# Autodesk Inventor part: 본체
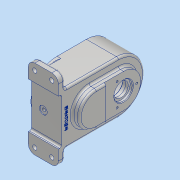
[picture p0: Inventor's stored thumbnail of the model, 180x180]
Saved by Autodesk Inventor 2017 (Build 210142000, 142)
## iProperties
Part Number: 본체
Material: 알루미늄 6061
Document SubType Name: Modeling
Designer: MRC
Density: 2.7 g/cm^3
Appearance: 알루미늄 - 평지
Mass: 756.755 g
Surface Area: 581.834 cm^2
Volume: 280.28 cm^3
Author: MRC
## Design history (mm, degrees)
sketch "스케치1"
  geometry: L1 (0, 40)-(-82, 40); L2 (-82, 40)-(-82, 61); L3 (-82, 61)-(-92, 61); L4 (-92, 61)-(-92, 35); L5 (-92, 35)-(-87, 35); L6 (-87, 35)-(-87, -35); L7 (-87, -35)-(-92, -35); L8 (-92, -35)-(-92, -61); L9 (-92, -61)-(-82, -61); L10 (-82, -61)-(-82, -40); L11 (-82, -40)-(0, -40); A1 r 40 centre (0, 0) between (0, -40) and (0, 40); 1 further point
  constraints: 22 end point, 6 perpendicular, 3 point on line, 2 horizontal, 2 point on circle, 2 tangent, 1 centre point, 1 coincident, 1 parallel, 1 vertical
  dimensions: "d0" = 80 diameter of A1; "d1" = 92 distance from line of L8 point (0, 0); "d2" = 10 distance of L8.end L9.end; "d3" = 70 distance between parallel lines of L7 L5; "d4" = 35 distance from line of L7 point (0, 0); "d5" = 5 distance between parallel lines of L8 L6; "d6" = 122 distance between parallel lines of L3 L9; "d7" = 61 distance from line of point (0, 0) L9
extrude "돌출1" new body sketch "스케치1" distance "d8" = 46; taper "d9" = 0 deg
sketch "스케치2"
  geometry: L1 (-40, 0)-(-40, -82) reference; L2 (40, -82)-(40, 0) reference; L3 (-40, -82)-(-40, 0) reference; L4 (-40, 0)-(-40, -45); L5 (40, 0)-(40, -45); A1 r 40 centre (0, 0) between (40, 0) and (-40, 0) reference; A2 r 40 centre (0, -45) between (-40, -45) and (40, -45); A3 r 40 centre (0, 0) between (40, 0) and (-40, 0); A4 r 40 centre (0, 0) between (40, 0) and (-40, 0) reference
  constraints: 6 end point, 4 point on circle, 2 centre point, 2 point on line, 2 tangent, 1 coincident, 1 concentric, 1 vertical
  dimensions: "d10" = 45 distance of A2.centre A1.centre
extrude "돌출2" join sketch "스케치2" distance "d11" = 3; taper "d12" = 0 deg
sketch "스케치3"
  geometry: L1 (0, 0)-(0, -45); L2 (-26, 0)-(-26, -45); L3 (26, -45)-(26, 0); A1 r 40 centre (0, 0) between (40, 0) and (-40, 0) reference; A2 r 26 centre (0, 0) between (26, 0) and (-26, 0); A3 r 26 centre (0, -45) between (-26, -45) and (26, -45); 1 further point
  constraints: 8 end point, 4 point on circle, 4 tangent, 2 centre point, 1 midpoint, 1 parallel, 1 vertical
  dimensions: "d13" = 52 diameter of A3; "d14" = 45 distance of L1.end L1.start
extrude "돌출3" join sketch "스케치3" distance "d15" = 11; taper "d16" = 0 deg
sketch "스케치4"
  geometry: L1 (-26, 0)-(-26, -45) reference; L2 (26, -45)-(26, 0) reference; L3 (-26, -30)-(26, -30); A1 r 26 centre (0, 0) between (26, 0) and (-26, 0) reference
  constraints: 2 end point, 2 point on line, 1 horizontal
  dimensions: "d17" = 30 distance from line of L3 A1.centre
extrude "돌출4" cut sketch "스케치4" distance "d18" = 3; taper "d19" = 0 deg
sketch "스케치5"
  geometry: L1 (0, 0)-(0, -45); L2 (30, 0)-(30, -45); L3 (-30, -45)-(-30, 0); A1 r 40 centre (0, 0) between (40, 0) and (-40, 0) reference; A2 r 40 centre (0, -45) between (-40, -45) and (40, -45) reference; A3 r 30 centre (0, 0) between (30, 0) and (-30, 0); A4 r 30 centre (0, -45) between (-30, -45) and (30, -45); 1 further point
  constraints: 8 end point, 4 point on circle, 4 tangent, 2 centre point, 1 midpoint, 1 parallel, 1 vertical
  dimensions: "d20" = 30 radius of A3
extrude "돌출5" cut sketch "스케치5" distance "d21" = 41; taper "d22" = 0 deg
hole "구멍1" diameter "d25" = 20; stored, may be unused: countersink angle "d29" = 90 deg, drill point angle "d31" = 0 deg; dims "d23" = 10, "d24" = 10, "d26" = 6, "d27" = 28, "d28" = 8, "d30" = 12
sketch "스케치6"
  geometry: C1 r 14 at (0, 0); A1 r 30 centre (0, 0) between (30, 0) and (-30, 0) reference
  constraints: 1 centre point, 1 coincident
  dimensions: "d32" = 28 diameter of C1
extrude "돌출6" cut sketch "스케치6" distance "d33" = 8; taper "d34" = 0 deg
hole "구멍2" diameter "d37" = 22; stored, may be unused: countersink angle "d41" = 90 deg, drill point angle "d43" = 0 deg; dims "d35" = 10, "d36" = 10, "d38" = 6, "d39" = 28, "d40" = 4, "d42" = 20
node "작업 평면2"
sketch "스케치8"
  geometry: L1 (-3, 5)-(-3, -75) reference; C1 r 6 at (18, -35); 1 further point
  constraints: 1 centre point, 1 horizontal alignment
  dimensions: "d45" = 12 diameter of C1; "d46" = 21 distance from line of L1 C1.centre
extrude "돌출7" join sketch "스케치8" stored distance "d47" = 8; taper "d48" = 0 deg
sketch "스케치9"
  geometry: C1 r 6 at (0, 0) reference; 1 further point
hole "구멍3" sketch "스케치9" at (0, 0) diameter "d49" = 4.917; stored, may be unused: countersink angle "d53" = 90 deg, drill point angle "d55" = 118 deg; dims "d50" = 12, "d51" = 19.05, "d52" = 4.775, "d54" = 17.1
sketch "스케치10"
  geometry: L1 (0, 0)-(0, 70) reference; L2 (-3, 75)-(-3, -5) reference; 3 further points
  constraints: 1 horizontal alignment, 1 midpoint
  dimensions: "d56" = 21 distance from line of L2 point (18, 35)
hole "구멍4" sketch "스케치10" at (18, 35) diameter "d57" = 4.917; stored, may be unused: countersink angle "d61" = 90 deg, drill point angle "d63" = 118 deg; dims "d58" = 12, "d59" = 12, "d60" = 1, "d62" = 17.1
sketch "스케치11"
  geometry: L1 (0, 0)-(0, -45); L2 (35, 0)-(35, -45); L3 (-35, -45)-(-35, 0); C1 r 11 at (0, 0) reference; A1 r 40 centre (0, -45) between (-40, -45) and (40, -45) reference; A2 r 35 centre (0, 0) between (35, 0) and (-35, 0); A3 r 35 centre (0, -45) between (-35, -45) and (35, -45); 7 further points
  constraints: 8 end point, 6 point on circle, 4 coincident, 4 tangent, 2 centre point, 1 midpoint, 1 parallel, 1 vertical
  dimensions: "d64" = 35 radius of A2
hole "구멍5" sketch "스케치11" at (0, 35), (-35, 0), (35, 0), (35, -45), (0, -80), (-35, -45) diameter "d65" = 3.242; stored, may be unused: countersink angle "d69" = 90 deg, drill point angle "d71" = 118 deg; dims "d66" = 8, "d67" = 12, "d68" = 1, "d70" = 10
sketch "스케치12"
  geometry: C1 r 14 at (0, 0) reference; 1 further point
  constraints: 1 vertical alignment
  dimensions: "d72" = 20 distance of point (0, 20) C1.centre
hole "구멍6" sketch "스케치12" at (0, 20) diameter "d73" = 3.242; stored, may be unused: countersink angle "d77" = 90 deg, drill point angle "d79" = 118 deg; dims "d74" = 8, "d75" = 12, "d76" = 1, "d78" = 10
fillet "모깎기1" dims "d83" = 10
sketch "스케치13"
  geometry: L1 (10, 101)-(36, 101) reference; L2 (0, 80)-(0, 91) reference; L3 (0, 80)-(46, 80) reference; L4 (46, 91)-(46, 80) reference; A1 r 10 centre (36, -11) between (36, -21) and (46, -11) reference; A2 r 10 centre (10, -11) between (0, -11) and (10, -21) reference; A3 r 10 centre (36, 91) between (46, 91) and (36, 101) reference; A4 r 10 centre (10, 91) between (10, 101) and (0, 91) reference; 1 further point
hole "구멍7" sketch "스케치13" at (36, -11), (10, -11), (10, 91), (36, 91) diameter "d84" = 6.6; stored, may be unused: countersink angle "d88" = 90 deg, drill point angle "d90" = 118 deg; dims "d85" = 8, "d86" = 11, "d87" = 2, "d89" = 20
fillet "모깎기2" dims "d91" = 3
fillet "모깎기3" dims "d92" = 5
fillet "모깎기4" dims "d93" = 0.3
fillet "모깎기5" dims "d94" = 3
fillet "모깎기6" dims "d95" = 3
chamfer "모따기1" distance "d96" = 1; stored, may be unused: second distance "d97" = 2, angle "d98" = 45 deg
sketch "스케치14"
  geometry: L1 (-32, -87)-(32, -87) reference; L2 (-51, -92)-(-61, -92) reference; 2 further points
  constraints: 1 midpoint, 1 vertical alignment, 1 other
  dimensions: "d100" = 12 distance from line of L2 point (0, -80)
feature "엠보싱1" sketch "스케치14" dims "d0" = 80, "d1" = 92, "d2" = 10, "d3" = 70, "d4" = 35, "d5" = 5, "d6" = 122, "d7" = 61, "d10" = 45, "d101" = 0.5, "d102" = 0
node "솔리드1"
pattern_circular "원형 패턴1" dims angle "d81" = 360 deg
node "투영된 루프1"
other parameters: "d44" = -135
